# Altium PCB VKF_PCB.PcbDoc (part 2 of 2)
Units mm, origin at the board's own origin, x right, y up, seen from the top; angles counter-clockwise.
Board outline 125 x 80 mm, 4 copper layers (Top Layer, Mid-Layer 1, Mid-Layer 2, Bottom Layer), stack 1.633 mm thick; 104 components, 58 nets, 332 pads, 515 vias.
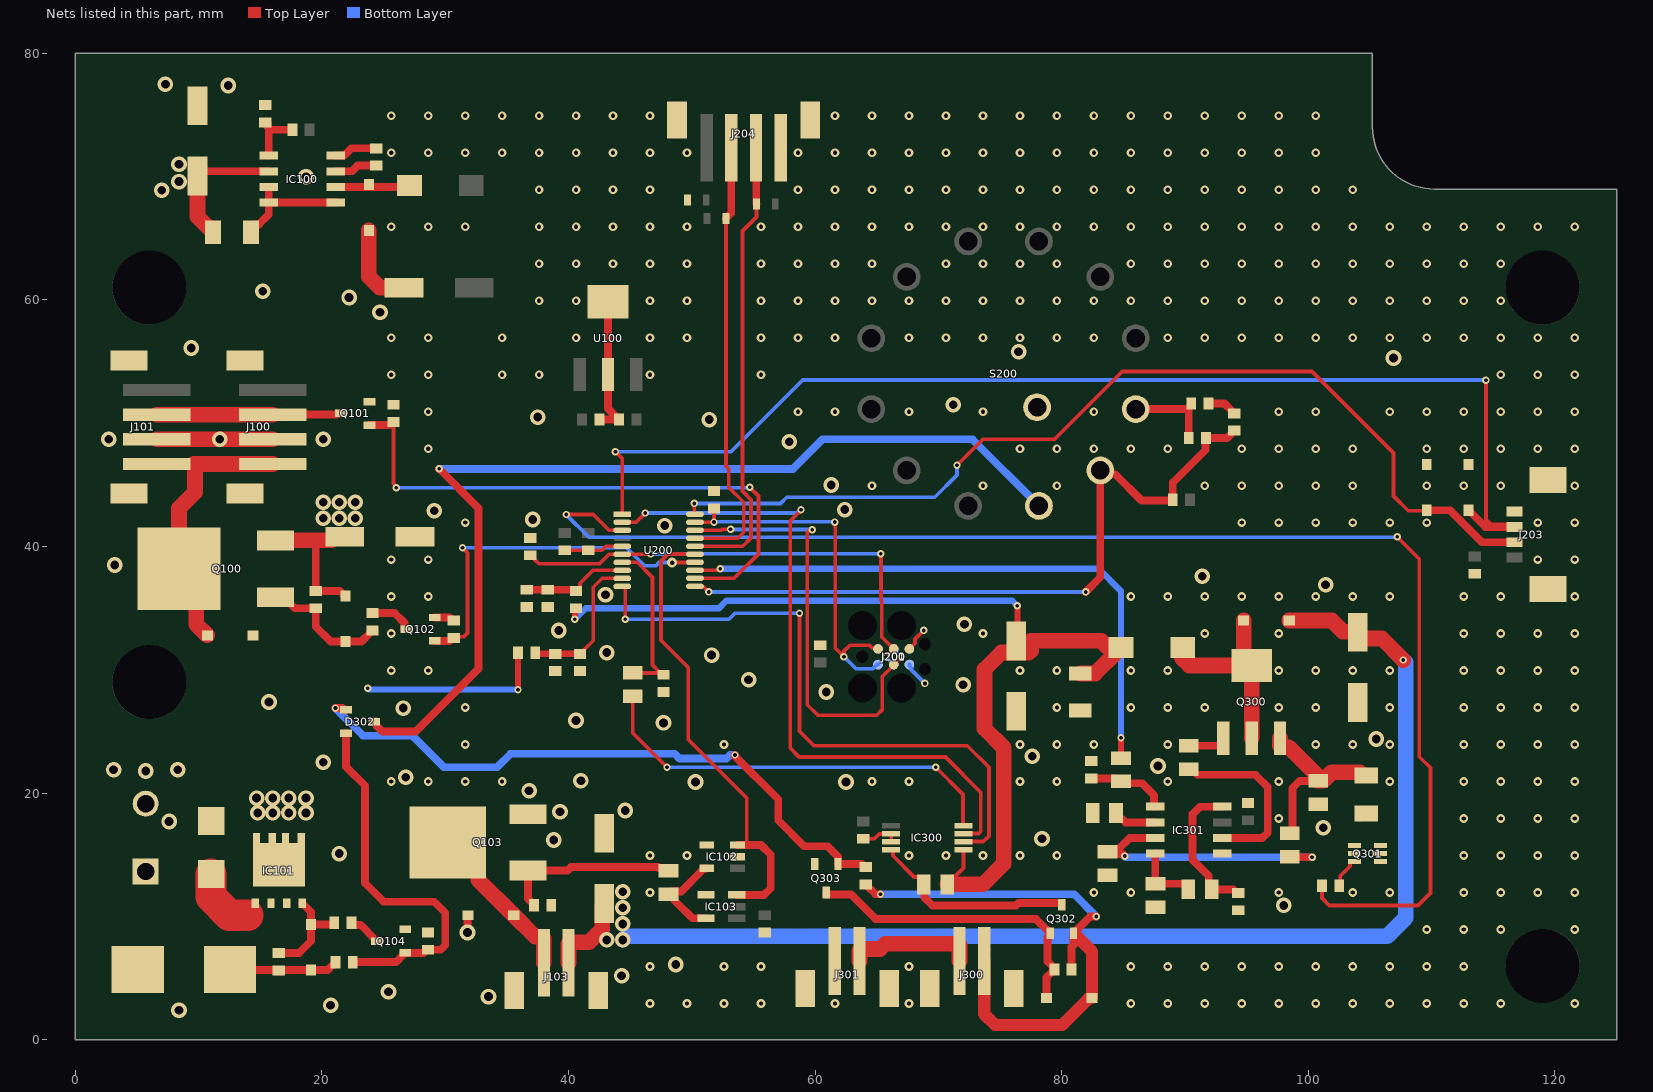
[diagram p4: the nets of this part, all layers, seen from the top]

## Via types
v1: diameter 0.7, hole 0.35, Top Layer to Bottom Layer, 373 vias
v2: diameter 1.27, hole 0.711, Top Layer to Bottom Layer, tented both sides, 89 vias
v3: diameter 0.6, hole 0.3, Top Layer to Bottom Layer, tented both sides, 52 vias
v4: diameter 0.8, hole 0.35, Top Layer to Bottom Layer, 1 vias

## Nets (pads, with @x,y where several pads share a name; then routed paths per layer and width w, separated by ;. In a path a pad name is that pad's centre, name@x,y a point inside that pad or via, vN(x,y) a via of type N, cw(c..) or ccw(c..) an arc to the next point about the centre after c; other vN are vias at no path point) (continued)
GND: C100.2 C101.2 C102.2 C103.2 C104.2 C105.2 C106.2 C107.2 C200.2 C201.2 C202.2 C203.2 C205.2 C206.2 C207.1 C300.2 C301.2 C302.2 C303.2 C304.2 C305.2 C306.2 C307.2 C308.2 C309.2 C310.2 C311.2 D100.2 D102.2 D105.2 D201.2 D202.2 IC100.4 IC102.2 IC102.4 IC103.4 IC300.6 IC300.7 IC301.5 J100.2 J100.5 J100.6 J101.2 J101.5 J101.6 J102.2 J103.3 J103.4 J200.6 J201.6 J203.4 J203.5 J203.6 J204.4 J204.MP1 J204.MP2 J300.3 J300.4 J301.2 J301.3 J301.4 Q101.2 Q102.2 Q103.3 Q104.2 Q301.4 Q303.2 R104.1 R105.2 R106.1 R110.2 R112.1 R204.1 R205.1 R303.1 R304.1 R307.1 R309.1 S200.A1 U100.2 U200.5 | length 47.5
  Top Layer w0.305: C202.2@39.7,39.7 C201.2@41.6,39.7 42.7,39.7 43.025,40.025 U200.5@44.35,40.025 ; C302.2@63.9,16.3 64.8,16.3 65.194,16.694 66.131,16.694 IC300.6@66.162,16.725 IC300.7@66.162,16.075 ; J200.6@67.64,31.7 68.1,32.16 68.1,32.5 v3(68.8,33.2)
  Top Layer w0.635: IC100.4@21.112,71.705 21.12,71.713 21.813,71.713 22.4,72.3 C103.2@24.4,72.3 ; Q102.2@29.15,34.25 30.35,34.25 30.6,34 R105.2@30.7,34 ; C104.2@42.5,50.3 C105.2@44.1,50.3 44.1,50.4 44.017,50.483 43.917,50.483 43.2,51.2 U100.2@43.2,53.95 U100.2@43.2,59.85 ; R204.1@91.9,51.6 93.2,51.6 93.817,50.983 93.817,50.883 93.9,50.8 C205.2@94,50.8
  Top Layer w1.27: J101.2@6.6,48.7 J100.2@16,48.7 ; D102.2@23.8,65.65 23.8,61.9 24.7,61 C101.2@26.65,61
  Bottom Layer w0.305: J201.6@67.64,30.43 67.64,30.3 67.814,30.126 67.814,29.986 v3(68.9,28.9)
  other v1: 46.607,2.946 49.607,2.946 52.607,2.946 55.607,2.946 61.607,2.946 67.607,2.946 85.607,2.946 88.607,2.946 91.607,2.946 94.607,2.946 97.607,2.946 100.607,2.946 103.607,2.946 106.607,2.946 109.607,2.946 112.607,2.946 115.607,2.946 121.607,2.946 46.607,5.946 52.607,5.946 55.607,5.946 67.607,5.946 85.607,5.946 88.607,5.946 91.607,5.946 94.607,5.946 97.607,5.946 100.607,5.946 103.607,5.946 106.607,5.946 109.607,5.946 112.607,5.946 109.607,8.946 112.607,8.946 115.607,8.946 121.607,8.946 46.607,11.946 82.607,11.946 85.607,11.946 97.607,11.946 103.607,11.946 106.607,11.946 112.607,11.946 115.607,11.946 118.607,11.946 121.607,11.946 46.607,14.946 49.607,14.946 67.607,14.946 70.607,14.946 73.607,14.946 76.607,14.946 79.607,14.946 112.607,14.946 115.607,14.946 118.607,14.946 121.607,14.946 97.607,17.946 112.607,17.946 115.607,17.946 118.607,17.946 121.607,17.946 25.607,20.946 28.607,20.946 31.607,20.946 34.607,20.946 64.607,20.946 67.607,20.946 76.607,20.946 79.607,20.946 88.607,20.946 97.607,20.946 106.607,20.946 112.607,20.946 115.607,20.946 118.607,20.946 121.607,20.946 31.607,23.946 52.607,23.946 76.607,23.946 79.607,23.946 82.607,23.946 88.607,23.946 100.607,23.946 103.607,23.946 106.607,23.946 112.607,23.946 115.607,23.946 118.607,23.946 121.607,23.946 31.607,26.946 79.607,26.946 85.607,26.946 88.607,26.946 91.607,26.946 97.607,26.946 100.607,26.946 106.607,26.946 112.607,26.946 115.607,26.946 118.607,26.946 121.607,26.946 25.607,29.946 28.607,29.946 76.607,29.946 79.607,29.946 85.607,29.946 88.607,29.946 97.607,29.946 100.607,29.946 103.607,29.946 106.607,29.946 112.607,29.946 115.607,29.946 118.607,29.946 121.607,29.946 25.607,32.946 73.607,32.946 91.607,32.946 97.607,32.946 112.607,32.946 115.607,32.946 118.607,32.946 121.607,32.946 25.607,35.946 28.607,35.946 85.607,35.946 88.607,35.946 91.607,35.946 94.607,35.946 97.607,35.946 100.607,35.946 103.607,35.946 106.607,35.946 112.607,35.946 115.607,35.946 121.607,35.946 25.607,38.946 28.607,38.946 118.607,38.946 121.607,38.946 31.607,41.946 94.607,41.946 97.607,41.946 100.607,41.946 103.607,41.946 106.607,41.946 109.607,41.946 118.607,41.946 121.607,41.946 64.607,44.946 73.607,44.946 79.607,44.946 91.607,44.946 94.607,44.946 97.607,44.946 100.607,44.946 103.607,44.946 109.607,44.946 112.607,44.946 115.607,44.946 121.607,44.946 28.607,47.946 76.607,47.946 79.607,47.946 82.607,47.946 85.607,47.946 88.607,47.946 94.607,47.946 97.607,47.946 100.607,47.946 103.607,47.946 109.607,47.946 112.607,47.946 115.607,47.946 118.607,47.946 121.607,47.946 28.607,50.946 58.607,50.946 61.607,50.946 67.607,50.946 73.607,50.946 82.607,50.946 97.607,50.946 100.607,50.946 106.607,50.946 109.607,50.946 112.607,50.946 115.607,50.946 118.607,50.946 121.607,50.946 25.607,53.946 28.607,53.946 34.607,53.946 37.607,53.946 46.607,53.946 55.607,53.946 115.607,53.946 118.607,53.946 121.607,53.946 25.607,56.946 28.607,56.946 34.607,56.946 40.607,56.946 46.607,56.946 49.607,56.946 55.607,56.946 58.607,56.946 61.607,56.946 67.607,56.946 70.607,56.946 73.607,56.946 76.607,56.946 79.607,56.946 82.607,56.946 88.607,56.946 91.607,56.946 94.607,56.946 97.607,56.946 100.607,56.946 103.607,56.946 106.607,56.946 109.607,56.946 112.607,56.946 115.607,56.946 118.607,56.946 121.607,56.946 37.607,59.946 40.607,59.946 46.607,59.946 49.607,59.946 55.607,59.946 58.607,59.946 61.607,59.946 64.607,59.946 67.607,59.946 70.607,59.946 73.607,59.946 76.607,59.946 79.607,59.946 82.607,59.946 85.607,59.946 88.607,59.946 91.607,59.946 94.607,59.946 97.607,59.946 100.607,59.946 103.607,59.946 106.607,59.946 109.607,59.946 112.607,59.946 115.607,59.946 37.607,62.946 40.607,62.946 43.607,62.946 46.607,62.946 49.607,62.946 55.607,62.946 58.607,62.946 61.607,62.946 64.607,62.946 70.607,62.946 73.607,62.946 76.607,62.946 79.607,62.946 85.607,62.946 88.607,62.946 91.607,62.946 94.607,62.946 97.607,62.946 100.607,62.946 103.607,62.946 106.607,62.946 109.607,62.946 112.607,62.946 115.607,62.946 25.607,65.946 28.607,65.946 31.607,65.946 37.607,65.946 40.607,65.946 43.607,65.946 46.607,65.946 49.607,65.946 55.607,65.946 58.607,65.946 61.607,65.946 64.607,65.946 67.607,65.946 70.607,65.946 73.607,65.946 76.607,65.946 79.607,65.946 82.607,65.946 85.607,65.946 88.607,65.946 91.607,65.946 94.607,65.946 97.607,65.946 100.607,65.946 103.607,65.946 106.607,65.946 109.607,65.946 112.607,65.946 115.607,65.946 118.607,65.946 121.607,65.946 37.607,68.946 40.607,68.946 43.607,68.946 46.607,68.946 58.607,68.946 61.607,68.946 64.607,68.946 67.607,68.946 70.607,68.946 73.607,68.946 76.607,68.946 79.607,68.946 82.607,68.946 85.607,68.946 88.607,68.946 91.607,68.946 94.607,68.946 97.607,68.946 100.607,68.946 103.607,68.946 25.607,71.946 28.607,71.946 31.607,71.946 34.607,71.946 37.607,71.946 40.607,71.946 43.607,71.946 46.607,71.946 49.607,71.946 58.607,71.946 61.607,71.946 64.607,71.946 67.607,71.946 70.607,71.946 73.607,71.946 76.607,71.946 79.607,71.946 82.607,71.946 85.607,71.946 88.607,71.946 91.607,71.946 94.607,71.946 97.607,71.946 100.607,71.946 25.607,74.946 28.607,74.946 31.607,74.946 34.607,74.946 37.607,74.946 40.607,74.946 43.607,74.946 46.607,74.946 61.607,74.946 64.607,74.946 67.607,74.946 70.607,74.946 73.607,74.946 76.607,74.946 79.607,74.946 82.607,74.946 85.607,74.946 88.607,74.946 91.607,74.946 94.607,74.946 97.607,74.946 100.607,74.946
  other v2: 8.4,2.4 20.7,2.8 33.5,3.5 25.4,3.9 44.3,5.2 48.7,6.1 98,10.9 21.4,15.1 38.8,16.2 78.4,16.3 101.2,17.2 7.6,17.7 39.3,18.5 44.6,18.6 36.8,20.2 50.3,20.9 62.5,20.9 41,21 26.8,21.3 5.7,21.8 3.1,21.9 8.3,21.9 87.8,22.2 20.1,22.5 77.6,23 105.5,24.4 47.7,25.7 40.6,25.9 26.6,26.9 15.7,27.4 60.9,28.2 72,28.8 54.6,29.2 51.6,31.2 43.1,31.4 39.2,33.2 72.1,33.7 43,36.1 101.4,36.898 91.4,37.6 3.2,38.5 47.8,41.7 37.1,42.2 29.1,42.9 62.4,43 61.3,45 57.9,48.5 2.7,48.7 11.7,48.7 20.1,48.7 51.4,50.3 37.5,50.5 71.2,51.5 106.9,55.3 76.5,55.8 9.4,56.1 24.7,59 22.2,60.2 15.2,60.7 18.7,70 12.4,77.4 7.3,77.5
NetC103_1: C103.1 IC100.3 | length 3.5
  Top Layer w0.635: IC100.3@21.112,70.435 22.435,70.435 22.9,70.9 C103.1@24.4,70.9
NetC300_1: C300.1 R301.1 R303.2 U200.8 | length 8.6
  Top Layer w0.305: R301.1@40.4,36.5 40.771,36.5 40.918,36.648 40.918,37.018 41.975,38.075 U200.8@44.35,38.075
  Top Layer w0.635: R303.2@36.6,36.5 C300.1@38.3,36.5 R301.1@40.4,36.5
NetC301_1: C301.1 R302.1 R304.2 U200.9 | length 12.2
  Top Layer w0.305: C301.1@40.93,31.3 41.03,31.3 41.278,31.548 41.278,31.648 42,32.37 42,36.7 42.725,37.425 U200.9@44.35,37.425
  Top Layer w0.508: R302.1@37.3,31.4 37.4,31.3 R304.2@38.93,31.3 C301.1@40.93,31.3
NetC303_1: C303.1 R305.2 U200.7 | length 13.4
  Top Layer w0.305: U200.7@44.35,38.725 45.575,38.725 46.8,37.5 46.8,30.4 47.352,29.848 C303.1@47.45,29.75 ; R305.2@45.2,29.75 C303.1@47.45,29.75 ; C303.1@47.6,29.6 C303.1@47.45,29.75
NetC307_1: C307.1 IC301.1 R306.2 | length 6.7
  Top Layer w0.635: C307.1@82.4,21.2 84.3,21.2 84.55,20.95 R306.2@84.8,20.95 84.95,20.8 86.5,20.8 87.489,19.811 87.489,18.913 87.497,18.905 IC301.1@87.588,18.905
NetC309_1: C309.1 IC301.4 R311.1 | length 5.4
  Top Layer w0.635: IC301.4@87.588,15.095 87.588,12.662 C309.1@87.6,12.65 90.017,12.65 90.25,12.418 R311.1@90.25,12.2
NetC310_1: C310.1 IC301.8 R311.2 | length 11.7
  Top Layer w0.635: IC301.8@93.012,18.905 91.205,18.905 90.6,18.3 90.6,14.6 91.917,13.283 91.917,12.433 R311.2@92.15,12.2 93.9,12.2 94.2,11.9 C310.1@94.3,11.9
NetC311_1: C311.1 IC301.3 R313.1 | length 23
  Top Layer w0.635: v3(85.1,14.9) 84.939,15.061 83.889,15.061 C311.1@83.7,15.25 83.933,15.483 84.633,15.483 85.515,16.365 IC301.3@87.588,16.365 ; R313.1@98.5,14.85 98.55,14.8 v3(100.3,14.8)
  Bottom Layer w0.635: v3(85.1,14.9) 85.2,14.8 v3(100.3,14.8)
NetD100_1: D100.1 J100.1 J101.1 Q100.2 | length 21.8
  Top Layer w1.27: D100.1@10.7,32.8 9.811,33.689 9.811,36.789 Q100.2@8.4,38.2 8.4,43.1 9.7,44.4 9.7,46.6 9.6,46.7 J100.1@16,46.7
NetD101_2: D101.2 Q100.1 R101.2 R103.2 | length 10.7
  Top Layer w0.635: Q100.1@16.25,35.9 16.95,35.9 17.433,35.418 17.433,35.372 17.804,35 R101.2@19.5,35 19.5,33.5 20.7,32.3 D101.2@21.9,32.3 23.2,32.3 23.917,33.017 23.917,33.117 24,33.2 R103.2@24.1,33.2
NetD102_1: D102.1 IC100.2 L100.2 | length 6
  Top Layer w0.635: IC100.2@21.112,69.165 26.965,69.165 L100.2@27.1,69.3
NetD103_2: D103.2 J103.2 Q103.2 | length 13.4
  Top Layer w1.27: Q103.2@30.2,16 30.4,16 32.665,13.735 32.665,12.985 D103.2@35.55,10.1 37.285,8.365 37.865,8.365 38,8.23 J103.2@38,6.25
NetD104_1: D104.1 D105.1 F100.2 IC101.1 IC101.2 IC101.3 R107.2 R111.2 | length 14.9
  Top Layer w0.635: F100.2@12.591,5.746 F100.2@12.545,5.7 12.595,5.65 D104.1@19.1,5.65 20.45,5.65 20.917,6.117 21.017,6.117 21.1,6.2 R111.2@21.1,6.3 ; R107.2@16.317,5.543 16.4,5.626 R107.2@16.5,5.626 16.6,5.626 R107.2@16.683,5.543
  Top Layer w2.54: D105.1@11,13.45 11,11.588 12.488,10.1 14,10.1
NetD104_2: D104.2 IC101.4 R107.1 R109.2 | length 8.4
  Top Layer w0.635: R107.1@16.5,7.026 18.126,7.026 19.1,8 D104.2@19.1,9.35 ; IC101.4@18.405,11.07 18.405,11.01 18.427,10.987 18.488,10.987 19.1,10.375 D104.2@19.1,9.35 ; R109.2@21,9.5 21,9.433 20.917,9.35 D104.2@19.1,9.35
NetD300_2: D300.2 L300.1 Q300.2 Q300.4 | length 15.9
  Top Layer w1.27: L300.1@89.725,31.125 89.725,30.975 90.35,30.35 Q300.4@95.4,30.35 ; D300.2@94.75,34 94.75,31 Q300.4@95.4,30.35 ; Q300.2@95.4,24.45 Q300.4@95.4,30.35
NetD301_1: D301.1 J300.1 Q302.2 R314.2 R315.2 | length 46.6
  Top Layer w0.635: R315.2@64.1,12.6 64.2,12.6 64.283,12.517 64.283,12.417 64.9,11.8 v3(65.3,11.8) ; J300.1@73.7,6.4 73.7,7.117 J300.1@73.883,7.3 ; R314.2@80.8,5.7 80.8,7.522 80.95,7.672 Q302.2@80.95,8.51 ; Q302.2@81.108,8.493 80.968,8.493 Q302.2@80.95,8.51 ; D301.1@82.152,3.317 82.317,3.317 82.317,3.483 82.4,3.4 D301.1@82.45,3.4 ; v3(82.8,10) 82.3,10 81.108,8.808 80.968,8.808 80.95,8.79 Q302.2@80.95,8.65 Q302.2@80.95,8.51
  Top Layer w1: J300.1@73.7,6.4 73.7,2.1 74.6,1.2 80.035,1.2 D301.1@82.152,3.317 ; Q302.2@81.108,8.493 82.45,7.15 D301.1@82.45,3.4
  Bottom Layer w0.635: v3(65.3,11.8) 81,11.8 v3(82.8,10)
NetD301_2: D301.2 Q302.1 Q303.3 R314.1 | length 25.6
  Top Layer w0.635: Q303.3@60.9,11.95 60.9,11.81 60.918,11.792 62.908,11.792 64.9,9.8 77.9,9.8 78.892,8.808 79.032,8.808 79.05,8.79 Q302.1@79.05,8.65 79.05,8.51 78.85,8.31 78.85,6.35 79.4,5.8 R314.1@79.4,5.7 79.4,5.6 79.317,5.517 79.217,5.517 78.75,5.05 D301.2@78.75,3.4
NetD302_1: D302.1 Q303.1 R315.1 | length 51.8
  Top Layer w0.635: v3(21.1,26.9) 21.66,26.9 21.81,26.75 D302.1@21.95,26.75 ; v3(53.5,23.1) 53.5,23 57,19.5 57,17.8 59.1,15.7 61,15.7 61.85,14.85 Q303.1@61.85,14.25 63.75,14.25 64,14 R315.1@64.1,14
  Bottom Layer w0.635: v3(21.1,26.9) 23.337,24.663 27.337,24.663 29.9,22.1 34.2,22.1 35.3,23.2 48.6,23.2 49,22.8 52.8,22.8 53.1,23.1 v3(53.5,23.1)
NetD302_2: D302.2 Q104.1 R111.1 R112.2 | length 30.6
  Top Layer w0.635: D302.2@21.95,24.85 21.95,22.15 23.5,20.6 23.5,12.7 25,11.2 29.1,11.2 30,10.3 30,7.672 29.628,7.3 R112.2@28.6,7.3 ; R111.1@22.5,6.3 26,6.3 26.592,6.892 26.592,7.032 26.61,7.05 Q104.1@26.75,7.05 R112.2@28.25,7.05
NetD302_3: D302.3 S200.1 | length 80.5
  Top Layer w0.635: D302.3@24.25,25.8 24.39,25.8 24.408,25.782 24.408,25.493 24.9,25 27.6,25 32.7,30.1 32.7,43.1 v3(29.5,46.3)
  Bottom Layer w0.635: v3(29.5,46.3) 58.2,46.3 60.6,48.7 72.75,48.7 S200.1@78.15,43.3
NetF100_1: F100.1 J102.1
NetIC100_1: IC100.1 IC100.7 IC100.8 R100.2 | length 9.9
  Top Layer w0.635: R100.2@14.25,65.5 14.25,65.8 14.583,66.133 14.883,66.133 15.688,66.938 IC100.8@15.688,67.895 ; IC100.7@15.688,69.165 IC100.8@15.688,67.895 ; IC100.1@21.112,67.895 IC100.8@15.688,67.895
NetIC100_5: IC100.5 R102.1 R104.2 | length 4.9
  Top Layer w0.635: R104.2@15.4,74.4 15.5,74.4 15.583,74.317 15.583,74.051 15.688,73.946 15.688,73.6 ; IC100.5@15.688,71.705 15.688,73.6 ; R102.1@17.6,73.8 15.888,73.8 15.688,73.6
NetIC102_3: IC102.3 IC103.3 U200.15 | length 37.7
  Top Layer w0.305: U200.15@50.25,39.375 49.371,39.375 49.343,39.402 48.066,39.402 47.5,38.836 47.5,32.4 49.708,30.192 49.708,24.359 54.458,19.609 54.458,15.892 54.55,15.8
  Top Layer w0.635: IC103.3@53.65,11.75 55.85,11.75 56.4,12.3 56.4,15 55.6,15.8 54.55,15.8 IC102.3@53.7,15.8
NetIC102_5: IC102.5 IC103.5 R108.1 | length 8
  Top Layer w0.635: IC103.5@51.15,9.85 50.05,9.85 48.583,11.317 48.583,11.567 48.35,11.8 R108.1@48.1,11.8 48.333,12.033 49.133,12.033 50.918,13.818 50.918,13.882 50.935,13.9 IC102.5@51.2,13.9
NetIC300_2: IC300.2 U200.10 | length 51.2
  Top Layer w0.305: U200.10@44.35,36.775 44.533,36.775 44.6,36.708 v3(44.6,34.1) ; v3(58.725,34.6) 58.725,25.019 59.893,23.851 72.339,23.851 74.092,22.098 74.092,16.535 73.631,16.075 IC300.2@72.038,16.075
  Bottom Layer w0.305: v3(44.6,34.1) 53,34.1 53.5,34.6 v3(58.725,34.6)
NetIC300_3: IC300.3 U200.2 | length 56.2
  Top Layer w0.305: U200.2@44.35,41.975 45.48,41.975 v3(46.228,42.723) ; v3(58.852,42.977) 58.852,42.951 57.988,42.088 57.988,23.647 58.699,22.936 70.561,22.936 73.431,20.066 73.431,16.904 73.253,16.725 IC300.3@72.038,16.725
  Bottom Layer w0.305: v3(46.228,42.723) 58.518,42.723 58.772,42.977 v3(58.852,42.977)
NetIC300_4: IC300.4 R305.1 | length 34.4
  Top Layer w0.305: R305.1@45.2,27.85 45.2,24.879 v3(47.981,22.098) ; v3(69.774,22.098) 71.984,19.888 71.984,17.429 IC300.4@72.038,17.375
  Bottom Layer w0.305: v3(47.981,22.098) v3(69.774,22.098)
NetIC300_8: IC300.8 Q302.3 R300.1 | length 16.9
  Top Layer w0.305: IC300.8@66.162,15.425 66.236,15.425 66.309,15.352 66.309,14.921 68.022,13.208 68.402,13.208 68.715,12.896 R300.1@68.715,12.515
  Top Layer w0.635: R300.1@68.8,12.6 68.864,12.536 68.864,11.536 69.5,10.9 76.3,10.9 76.5,11.1 79.982,11.1 80,11.083 Q302.3@80,10.95
NetIC301_2: IC301.2 R307.2 | length 3.7
  Top Layer w0.635: R307.2@84.4,18.4 84.4,18.15 84.633,17.918 84.882,17.918 85.165,17.635 IC301.2@87.588,17.635
NetIC301_6: IC301.6 R308.1 | length 14.6
  Top Layer w0.635: R308.1@90.3,21.95 90.55,21.95 91,21.5 95.7,21.5 96.7,20.5 96.7,16.8 96.265,16.365 IC301.6@93.012,16.365
NetJ100_3: J100.3 J101.3 Q101.3 | length 15
  Top Layer w0.635: J100.3@16,50.7 21.124,50.7 21.207,50.782 21.532,50.782 Q101.3@21.55,50.8
  Top Layer w1.27: J101.3@6.6,50.7 J100.3@16,50.7
NetJ300_2: J300.2 J301.1 | length 10.5
  Top Layer w1.27: J301.1@63.6,6.4 63.6,7.226 63.735,7.361 65.261,7.361 65.7,7.8 71.565,7.8 71.7,7.665 J300.2@71.7,6.4
NetQ101_1: Q101.1 R106.2 U200.12 | length 47.8
  Top Layer w0.305: R106.2@25.8,50.1 25.8,45.095 26.035,44.86 v3(26.035,44.78) ; U200.12@50.25,37.425 53.425,37.425 55.4,39.4 55.4,44.1 v3(54.7,44.8)
  Top Layer w0.635: Q101.1@23.85,49.85 25.45,49.85 25.7,50.1 R106.2@25.8,50.1
  Bottom Layer w0.305: v3(26.035,44.78) 54.68,44.78 v3(54.7,44.8)
NetQ102_1: Q102.1 R105.1 U200.14 | length 29.5
  Top Layer w0.305: R105.1@30.7,32.6 30.779,32.679 31.479,32.679 31.8,33 31.8,39.5 v3(31.4,39.9) ; v4(48.4,38.7) 48.413,38.713 50.237,38.713 U200.14@50.25,38.725
  Top Layer w0.635: Q102.1@29.15,32.35 30.35,32.35 30.6,32.6 R105.1@30.7,32.6
  Bottom Layer w0.305: v3(31.4,39.9) 44.7,39.9 46.15,38.45 47.083,38.45 47.333,38.7 v4(48.4,38.7)
NetQ102_3: Q102.3 R103.1 | length 3.6
  Top Layer w0.635: R103.1@24.1,34.6 25.9,34.6 26.692,33.808 26.692,33.318 26.71,33.3 Q102.3@26.85,33.3
NetQ103_1: Q103.1 R108.2 R110.1 | length 14.7
  Top Layer w0.635: R110.1@37.2,10.9 37.2,11 37.118,11.083 37.072,11.083 36.7,11.454 Q103.1@36.7,13.72 39.92,13.72 40.2,14 47.246,14 47.313,13.933 47.867,13.933 R108.2@48.1,13.7
NetQ104_3: Q104.3 R109.1 | length 2.8
  Top Layer w0.635: R109.1@22.4,9.5 22.4,9.4 22.483,9.317 23.133,9.317 24.292,8.157 24.292,8.017 24.31,8 Q104.3@24.45,8
NetQ300_1: Q300.1 R308.2 | length 3.9
  Top Layer w0.635: R308.2@89.817,24.083 90.05,23.85 R308.2@90.3,23.85 92.917,23.85 93.1,24.033 Q300.1@93.1,24.45
NetQ300_3: Q300.3 R309.2 R310.2 R313.2 | length 15.4
  Top Layer w0.635: R313.2@98.5,16.75 98.7,16.95 98.7,20.4 99.3,21 100.72,21 R309.2@100.8,21
  Top Layer w1.27: Q300.3@97.7,24.45 97.7,23.87 97.835,23.735 98.415,23.735 100.635,21.515 100.635,21.085 R309.2@100.72,21 ; R309.2@100.8,21 101.2,21 101.9,21.7 104.15,21.7 104.4,21.45 R310.2@104.7,21.45
NetQ301_1: Q301.1 Q301.2 Q301.5 Q301.6 R310.1 | length 0.8
  Top Layer w0.305: Q301.2@103.7,15.148 103.748,15.1 Q301.2@103.75,15.1 ; R310.1@104.207,17.857 R310.1@104.7,18.35
NetQ301_3: Q301.3 R312.1 | length 2.7
  Top Layer w0.305: R312.1@102.5,12.5 102.579,12.579 102.579,13.279 103.377,14.077 103.377,14.402 103.425,14.45 Q301.3@103.75,14.45
NetR203_1: R203.1 R204.2 S200.3 | length 7.1
  Top Layer w0.635: S200.3@85.999,51.149 90.149,51.149 R204.2@90.3,51.3 ; R203.1@90.3,48.8 R204.2@90.3,51.3 ; R204.2@90.5,51.5 R204.2@90.3,51.3
NetR306_1: R306.1 U200.13 | length 48.9
  Top Layer w0.305: U200.13@50.25,38.075 52.095,38.075 52.22,38.2 v3(52.3,38.2)
  Top Layer w0.508: R306.1@84.8,22.85 v3(84.8,24.5)
  Bottom Layer w0.508: v3(52.3,38.2) 83,38.2 84.8,36.4 v3(84.8,24.5)
NetR312_2: R312.2 U200.3 | length 113.7
  Top Layer w0.305: v3(39.8,42.6) 42,42.6 43.275,41.325 U200.3@44.35,41.325 ; R312.2@101.1,12.5 101.1,11.5 101.7,10.9 108.9,10.9 109.9,11.9 109.9,22.058 109,22.958 109,39 v3(107.2,40.8)
  Bottom Layer w0.305: v3(39.8,42.6) 41.651,40.749 107.149,40.749 v3(107.2,40.8)
RESET: C203.1 J200.4 J201.4 U200.6 | length 39.1
  Top Layer w0.305: C203.1@36.9,39.3 37,39.3 37.248,39.052 37.248,38.952 37.6,38.6 42.5,38.6 43.275,39.375 U200.6@44.35,39.375 46.639,39.375 v3(46.66,39.395) ; v3(65.329,39.421) 65.329,35.671 65.4,35.6 65.4,32.67 J200.4@66.37,31.7 ; v3(65.735,31.064) J200.4@66.37,31.7
  Bottom Layer w0.305: v3(46.66,39.395) 48.102,39.395 48.127,39.421 v3(65.329,39.421) ; v3(65.735,31.064) J201.4@66.37,30.43
SELECTEUR: C205.1 R201.1 R203.2 S200.2 U200.11 | length 57.9
  Top Layer w0.305: U200.11@50.25,36.775 50.278,36.747 50.934,36.747 v3(51.359,36.322)
  Top Layer w0.635: v3(81.94,36.322) 83.126,37.508 S200.2@83.126,46.173 83.435,45.864 84.337,45.864 86.462,43.739 88.939,43.739 R201.1@89,43.8 89,45.185 91.669,47.854 91.669,48.769 R203.2@91.7,48.8 93.4,48.8 93.817,49.217 93.817,49.317 93.9,49.4 C205.1@94,49.4
  Bottom Layer w0.305: v3(51.359,36.322) v3(81.94,36.322)
SYS_SWCLK: J200.2 J201.2 R205.2 U200.19 | length 30.6
  Top Layer w0.305: U200.19@50.25,41.975 51.779,41.975 v3(51.791,41.986) 51.791,43.009 R205.2@51.7,43.1 ; v3(61.595,41.986) 61.62,41.961 61.62,31.775 v3(62.33,31.065) 62.335,31.07 62.335,31.521 62.814,32 64.4,32 64.608,31.792 65.008,31.792 J200.2@65.1,31.7
  Bottom Layer w0.305: v3(51.791,41.986) 51.809,42.004 61.577,42.004 v3(61.595,41.986) ; v3(62.33,31.065) 63.295,30.1 64.68,30.1 65.01,30.43 J201.2@65.1,30.43
SYS_SWDIO: J200.3 J201.3 U200.18 | length 36.5
  Top Layer w0.305: U200.18@50.25,41.325 52.374,41.325 52.426,41.377 52.476,41.377 52.502,41.402 v3(53.137,41.402) ; v3(59.766,41.377) 59.588,41.377 59.36,41.148 59.36,27.178 60.223,26.314 64.999,26.314 65.43,26.746 65.43,29.439 66.37,30.378 J200.3@66.37,30.43 v3(67.005,31.064)
  Bottom Layer w0.305: v3(53.137,41.402) 53.188,41.351 53.213,41.377 v3(59.766,41.377) ; J201.3@66.37,31.7 v3(67.005,31.064)
TOF_SCL: J204.3 R206.1 U200.16 | length 37.3
  Top Layer w0.3: U200.16@50.25,40.025 54.125,40.025 54.8,40.7 54.8,43.8 54.1,44.5 54.1,65.6 55.238,66.738 R206.1@55.238,67.8
  Top Layer w0.635: J204.3@55.2,72.35 55.219,72.331 55.219,67.819 R206.1@55.238,67.8
TOF_SDA: J204.2 R207.1 U200.17 | length 36.1
  Top Layer w0.3: U200.17@50.25,40.675 53.714,40.675 54.2,41.161 54.2,43.6 53,44.8 53,46.3 52.762,46.538 R207.1@52.762,66.6
  Top Layer w0.635: R207.1@52.762,66.6 52.762,66.627 53.2,67.065 J204.2@53.2,72.35
UART2_RX: D202.1 J203.3 U200.1 | length 96.6
  Top Layer w0.305: v3(43.8,47.7) 44.35,47.15 U200.1@44.35,42.625 44.345,42.625 U200.1@44.272,42.698 ; v3(114.4,53.5) 114.4,42.2 114.8,41.8 116.5,41.8 J203.3@116.7,41.6
  Top Layer w0.635: D202.1@113,42.95 113,42.9 113.083,42.817 113.133,42.817 114.35,41.6 114.8,41.6 J203.3@116.7,41.6
  Bottom Layer w0.305: v3(43.8,47.7) 53.2,47.7 59,53.5 v3(114.4,53.5)
UART2_TX: D201.1 J203.2 U200.20 | length 80.1
  Top Layer w0.305: v3(50.2,43.5) 50.2,42.675 U200.20@50.25,42.625 ; v3(71.5,46.6) 73.6,48.7 79.4,48.7 84.9,54.2 100.3,54.2 106.9,47.6 106.9,44.1 108.1,42.9 D201.1@109.6,42.9
  Top Layer w0.635: D201.1@109.6,42.9 109.65,42.95 111.489,42.95 114.089,40.35 J203.2@116.7,40.35
  Bottom Layer w0.305: v3(50.2,43.5) 57.2,43.5 57.7,44 69.7,44 71.5,45.8 v3(71.5,46.6)
V_SOLAR: C304.1 C305.1 IC300.1 L300.2 R300.2 R301.2 | length 81.7
  Top Layer w0.305: R300.2@70.7,12.6 70.7,12.85 71.098,13.248 71.348,13.248 72.038,13.938 IC300.1@72.038,15.425
  Top Layer w0.508: v3(40.5,34.1) 40.518,34.118 40.518,34.918 R301.2@40.6,35 ; C305.1@76.3,32.35 76.4,32.45 v3(76.4,35.2)
  Top Layer w1.27: R300.2@70.7,12.6 73.6,12.6 75.3,14.3 75.3,23.684 73.736,25.248 73.736,30.036 75.11,31.41 77.335,31.41 77.5,31.575 77.5,32.35 83.2,32.35 83.65,31.9 L300.2@83.8,31.9 ; C304.1@81.5,29.7 82.7,29.7 84.435,31.435 84.435,31.585 84.65,31.8 L300.2@84.8,31.8
  Bottom Layer w0.508: v3(40.5,34.1) 41.4,35 52.2,35 52.8,35.6 76,35.6 v3(76.4,35.2)
VBAT: C100.1 C102.1 C106.1 C306.1 D101.1 D103.1 D300.1 IC100.6 IC101.5 IC101.6 IC101.7 IC101.8 IC101.9 J103.1 Q100.3 R100.1 R101.1 R302.2 | length 143.3
  Top Layer w0.508: v3(35.9,28.4) R302.2@35.9,31.4
  Top Layer w0.635: C102.1@9.9,70.05 10.285,70.435 IC100.6@15.688,70.435 ; 19.2,40.5 19.5,40.2 R101.1@19.5,36.4 21.446,36.4 21.713,36.132 21.817,36.132 21.9,36.05 D101.1@21.9,36 ; v2(31.8,8.7) 31.8,10.05 D103.1@31.85,10.1
  Top Layer w1.27: C102.1@9.9,70.05 9.9,66.75 10.835,65.815 11.135,65.815 11.15,65.8 R100.1@11.15,65.5 ; Q100.3@16.25,40.5 19.2,40.5 20.775,40.5 21.075,40.8 C100.1@21.85,40.8 ; J103.1@40,6.25 40,7.776 40.135,7.911 41.661,7.911 42.735,8.985 42.735,10.885 C106.1@42.9,11.05 ; D300.1@98.45,34 101.9,34 102.8,33.1 103.95,33.1 C306.1@104,33.05 104,32.704 104.165,32.539 105.961,32.539 v3(107.7,30.8)
  Bottom Layer w0.508: v3(23.7,28.5) 23.8,28.4 v3(35.9,28.4)
  Bottom Layer w1.27: v2(44.4,8.1) 44.7,8.4 106.4,8.4 107.9,9.9 107.9,30.6 v3(107.7,30.8)
  other v2: 43.1,8.1 44.4,9.4 44.4,10.7 44.4,12 14.8,18.4 16,18.4 17.3,18.4 18.7,18.4 14.7,19.6 16,19.6 17.3,19.6 18.7,19.6 20.1,42.3 21.4,42.3 22.7,42.3 20.1,43.6 21.4,43.6 22.7,43.6 7,68.9 8.4,69.6 8.4,71
pads on no net: IC103.1 J100.4 J101.4 J200.0 J200.5 J201.0 J201.5 S200.4 S200.5 S200.6 S200.7 S200.8 S200.9 S200.10 S200.11 S200.12

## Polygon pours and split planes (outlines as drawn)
3V3 on Mid-Layer 2 "Mid-Layer 2-3V3" (solid, pour order 2): 35,52.5 35,25 71.25,25 71.25,36.25 55,52.5
VBAT on Mid-Layer 2 "Mid-Layer 2-VBAT" (solid, pour order 0): 1.5,1.5 45,1.5 45,18.75 26.25,18.75 25,20 25,78.5 1.5,78.5
GND on Mid-Layer 1 "Mid-Layer 1-GND" (solid, pour order 4): 1.5,1.5 123.5,1.5 123.5,67.5 107.1,67.5 103.5,71.1 103.5,78.5 1.5,78.5
GND on Top Layer "Top Layer-GND" (solid, pour order 6): 1.5,1.5 123.5,1.5 123.5,67.5 107.1,67.5 103.5,71.1 103.5,78.5 1.5,78.5
GND on Bottom Layer "Bottom Layer-GND" (solid, pour order 10): 1.5,1.5 123.5,1.5 123.5,67.5 107.1,67.5 103.5,71.1 103.5,78.5 1.5,78.5

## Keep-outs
Keep-Out Layer:
  the board outline again, w0.4

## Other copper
Top Layer:
  rectangle net NetD104_1: 14.3,9.3 17.5,11.5
  rectangle net VBAT: 6.3,68.2 10.6,71.7
  rectangle net VBAT: 19.6,40 23.3,44.2
  rectangle net VBAT: 42.1,7.5 45,12.6
  rectangle net VBAT: 13.75,13.7 19.3,20.3
  region net NetQ301_1: 102.9,14.9 107,14.9 107,19 102.9,19
  region net NetF100_1: 7.1,3.9 7.1,14.8 7,14.9 3,14.9 3,3.9
  region net NetD104_1: 15.1,11.4 15,11.5 10.5,11.5 10.5,3.9 15.1,3.9

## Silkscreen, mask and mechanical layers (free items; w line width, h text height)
Top Overlay:
  circle w0.254: c119,6 r4
  circle w0.254: c119,61 r4
  circle w0.254: c6,61 r4
  circle w0.254: c6,29 r4
  lines w0.254: 0,0 125,0 125,69 110.2,69 cw(c110.2,74) 105.2,74 105.2,80 0,80 0,0
  text "VKF" at 94,75.9 h3
  text "Y : 43.3mm" at 92.1,60.3 h1
  text "X : 78.15mm" at 92.1,57.3 h1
